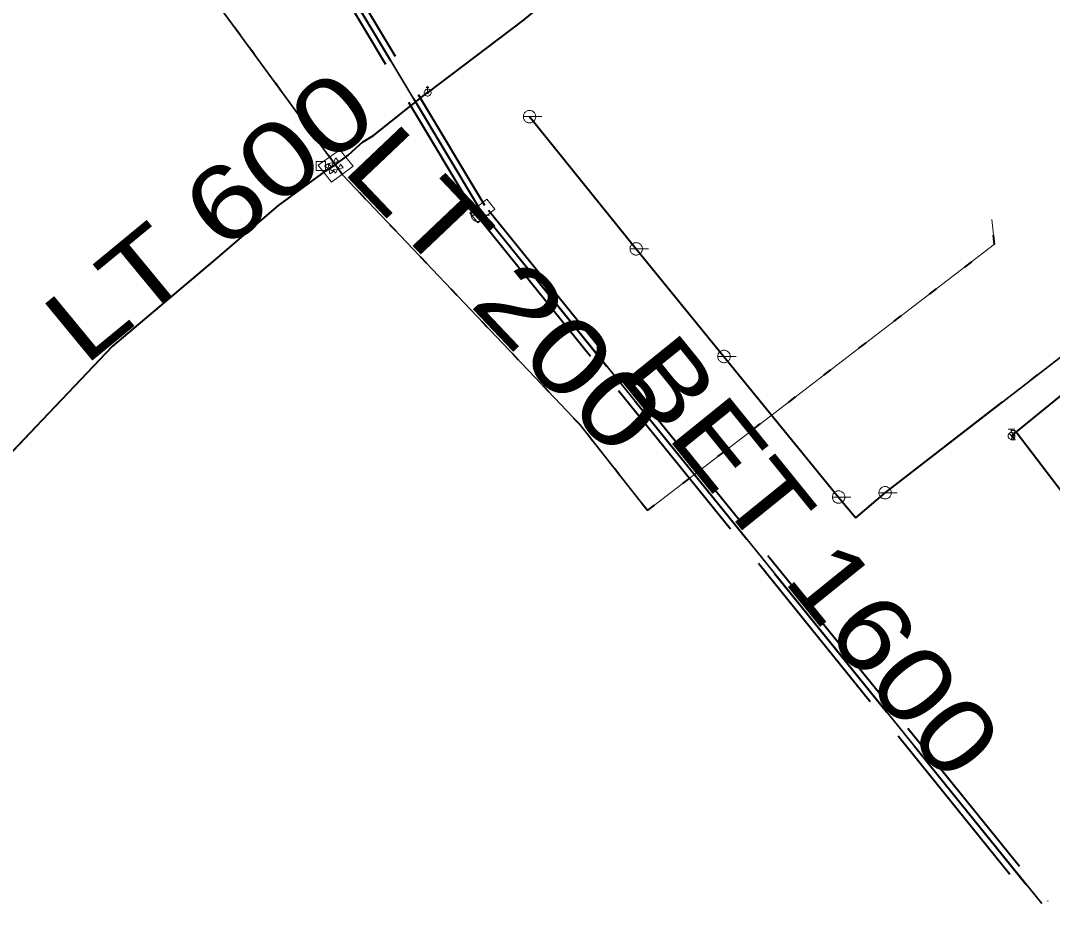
# Model space of a CAD drawing. Extents: x -968691 to -140888, y -1376050 to -879856.
# Drawn here: x -647839.9 to -647672.7, y -1059383.9 to -1059240 of the extents above; entities that cross this region are included whole.
import ezdxf
from ezdxf.enums import TextEntityAlignment as Align

# ---------------------------------------------------------------- set-up
doc = ezdxf.new("R2010")
doc.units = 0
doc.header["$LTSCALE"] = 4.8
for name, pattern in [('DASH_DOUBLE_DOT', [9.2, 5, -1.2, 0.3, -1.2, 0.3, -1.2]), ('DOTTED', [1.5, 0.3, -1.2]), ('LONG_DASHED', [7.5, 6, -1.5])]:
    doc.linetypes.add(name, pattern=pattern)
doc.layers.add('1', color=7, linetype='Continuous', lineweight=13)

msp = doc.modelspace()

# ---------------------------------------------------------------- hatches: boundary and pattern name
at = {"layer": '1'}
for points in [[(-647789.128, -1059263.115, 1), (-647789.288, -1059262.905, 1)], [(-647790.04, -1059264.101, 1), (-647789.819, -1059263.956, 1)], [(-647788.386, -1059264.131, 1), (-647788.546, -1059263.921, 1)], [(-647678.978, -1059307.23), (-647678.98, -1059307.206), (-647678.987, -1059307.183), (-647678.997, -1059307.161), (-647679.011, -1059307.142), (-647679.029, -1059307.125), (-647679.049, -1059307.112), (-647679.072, -1059307.103), (-647679.095, -1059307.099), (-647679.119, -1059307.098), (-647679.143, -1059307.102), (-647679.166, -1059307.11), (-647679.187, -1059307.122), (-647679.205, -1059307.138), (-647679.22, -1059307.157), (-647679.232, -1059307.178), (-647679.239, -1059307.201), (-647679.242, -1059307.225), (-647679.241, -1059307.249), (-647679.235, -1059307.272), (-647679.225, -1059307.294), (-647679.212, -1059307.314), (-647679.195, -1059307.331), (-647679.175, -1059307.345), (-647679.153, -1059307.355), (-647679.13, -1059307.361), (-647679.106, -1059307.362), (-647679.082, -1059307.359), (-647679.059, -1059307.352), (-647679.038, -1059307.341), (-647679.019, -1059307.326), (-647679.003, -1059307.307), (-647678.991, -1059307.287), (-647678.982, -1059307.264), (-647678.978, -1059307.24)]]:
    msp.add_hatch(color=256, dxfattribs=at).paths.add_polyline_path(points)

# ---------------------------------------------------------------- linework, layer by layer
at = {"layer": '1', "linetype": 'LONG_DASHED', "lineweight": 40}
for p, q in [((-647793.992, -1059221.085), (-647764.744, -1059269.917)), ((-647795.556, -1059222.364), (-647766.316, -1059271.182)), ((-647794.763, -1059221.744), (-647765.77, -1059270.15)), ((-647784.51, -1059259.7), (-647786.82, -1059261.82)), ((-647788.95, -1059263.39), (-647786.82, -1059261.82)), ((-647765.77, -1059270.15), (-647763.01, -1059273.68)), ((-647764.096, -1059270.746), (-647673.514, -1059382.739)), ((-647765.653, -1059272), (-647675.12, -1059383.932)), ((-647763.01, -1059273.68), (-647674.46, -1059383.16))]:
    msp.add_line(p, q, dxfattribs=at)
at = {"layer": '1', "lineweight": 35}
for p, q in [((-647794.763, -1059221.744), (-647765.77, -1059270.15)), ((-647789.208, -1059263.01), (-647804.27, -1059242.41)), ((-647784.51, -1059259.7), (-647786.82, -1059261.82)), ((-647788.95, -1059263.39), (-647789.208, -1059263.01)), ((-647788.95, -1059263.39), (-647786.82, -1059261.82)), ((-647765.77, -1059270.15), (-647763.01, -1059273.68)), ((-647763.01, -1059273.68), (-647674.46, -1059383.16)), ((-647699.84, -1059316.55), (-647668.01, -1059291.9)), ((-647666.74, -1059297), (-647678.59, -1059306.68)), ((-647704.573, -1059320.617), (-647699.84, -1059316.55))]:
    msp.add_line(p, q, dxfattribs=at)
at = {"layer": '1', "linetype": 'DOTTED', "lineweight": 40}
for p, q in [((-647789.208, -1059263.01), (-647804.27, -1059242.41)), ((-647788.95, -1059263.39), (-647789.208, -1059263.01))]:
    msp.add_line(p, q, dxfattribs=at)
at = {"layer": '1'}
for p, q in [((-647773.947, -1059251.688), (-647773.947, -1059250.696)), ((-647758.446, -1059255.581), (-647755.469, -1059255.581)), ((-647766.878, -1059271.56), (-647763.902, -1059271.56)), ((-647741.165, -1059277.018), (-647738.188, -1059277.018)), ((-647726.948, -1059294.462), (-647723.971, -1059294.462)), ((-647679.919, -1059306.271), (-647678.801, -1059306.271)), ((-647679.36, -1059306.782), (-647679.36, -1059306.271)), ((-647678.965, -1059307.736), (-647679.755, -1059306.945)), ((-647700.848, -1059316.55), (-647697.872, -1059316.55)), ((-647708.378, -1059317.25), (-647705.401, -1059317.25))]:
    msp.add_line(p, q, dxfattribs=at)
at = {"layer": '1', "linetype": 'DASH_DOUBLE_DOT'}
for p, q in [((-647791.704, -1059263.473), (-647788.166, -1059260.98)), ((-647788.166, -1059260.98), (-647786.015, -1059263.587)), ((-647789.532, -1059266.213), (-647791.704, -1059263.473)), ((-647786.015, -1059263.587), (-647789.532, -1059266.213))]:
    msp.add_line(p, q, dxfattribs=at)
at = {"layer": '1', "linetype": 'DASH_DOUBLE_DOT', "lineweight": 40}
for p, q in [((-647699.84, -1059316.55), (-647668.01, -1059291.9)), ((-647666.74, -1059297), (-647678.59, -1059306.68)), ((-647704.573, -1059320.617), (-647699.84, -1059316.55))]:
    msp.add_line(p, q, dxfattribs=at)
at = {"layer": '1', "linetype": 'DOTTED', "lineweight": 40}
for points in [[(-647804.27, -1059242.41), (-647812.48, -1059231.18), (-647819.495, -1059219.538)], [(-647738.337, -1059319.439), (-647749.311, -1059305.483), (-647787.758, -1059264.994), (-647788.466, -1059264.026), (-647788.95, -1059263.39)], [(-647738.337, -1059319.439), (-647682.104, -1059276.252), (-647682.55, -1059272.257)], [(-647678.59, -1059306.68), (-647679.11, -1059307.23), (-647679.36, -1059307.34)]]:
    msp.add_lwpolyline(points, dxfattribs=at)
at = {"layer": '1', "lineweight": 35}
for points in [[(-647804.27, -1059242.41), (-647812.48, -1059231.18), (-647819.495, -1059219.538)], [(-647773.946, -1059251.688), (-647773.795, -1059251.618), (-647758.476, -1059239.995), (-647755.985, -1059237.965), (-647755.346, -1059237.446)], [(-647784.51, -1059259.7), (-647782.725, -1059258.638), (-647773.946, -1059251.688)], [(-647757.438, -1059255.581), (-647740.157, -1059277.018), (-647725.94, -1059294.462), (-647707.37, -1059317.25), (-647704.573, -1059320.617)], [(-647790.53, -1059264.42), (-647798.147, -1059269.982), (-647808.729, -1059279.085), (-647824.987, -1059292.812), (-647847.758, -1059316.763), (-647852.291, -1059321.546), (-647857.02, -1059329.468), (-647864.807, -1059345.333), (-647870.759, -1059360.132), (-647875.166, -1059378.78)], [(-647790.53, -1059264.42), (-647789.929, -1059264.028), (-647788.95, -1059263.39)], [(-647738.337, -1059319.439), (-647749.311, -1059305.483), (-647787.758, -1059264.994), (-647788.466, -1059264.026), (-647788.95, -1059263.39)], [(-647678.59, -1059306.68), (-647658.06, -1059333.7), (-647656.38, -1059334.22), (-647654.638, -1059334.211)]]:
    msp.add_lwpolyline(points, dxfattribs=at)
at = {"layer": '1', "linetype": 'LONG_DASHED', "lineweight": 40}
for points in [[(-647773.946, -1059251.688), (-647773.795, -1059251.618), (-647758.476, -1059239.995), (-647755.985, -1059237.965), (-647755.346, -1059237.446)], [(-647784.51, -1059259.7), (-647782.725, -1059258.638), (-647773.946, -1059251.688)], [(-647790.53, -1059264.42), (-647789.929, -1059264.028), (-647788.95, -1059263.39)]]:
    msp.add_lwpolyline(points, dxfattribs=at)
at = {"layer": '1'}
for points in [[(-647773.388, -1059251.688), (-647773.396, -1059251.591), (-647773.421, -1059251.497), (-647773.463, -1059251.409), (-647773.518, -1059251.329), (-647773.587, -1059251.26), (-647773.667, -1059251.205), (-647773.755, -1059251.163), (-647773.849, -1059251.138), (-647773.946, -1059251.13), (-647774.044, -1059251.138), (-647774.138, -1059251.163), (-647774.226, -1059251.205), (-647774.306, -1059251.26), (-647774.375, -1059251.329), (-647774.43, -1059251.409), (-647774.472, -1059251.497), (-647774.497, -1059251.591), (-647774.505, -1059251.688), (-647774.497, -1059251.786), (-647774.472, -1059251.88), (-647774.43, -1059251.968), (-647774.375, -1059252.048), (-647774.306, -1059252.117), (-647774.226, -1059252.172), (-647774.138, -1059252.214), (-647774.044, -1059252.239), (-647773.946, -1059252.247), (-647773.849, -1059252.239), (-647773.755, -1059252.214), (-647773.667, -1059252.172), (-647773.587, -1059252.117), (-647773.518, -1059252.048), (-647773.463, -1059251.968), (-647773.421, -1059251.88), (-647773.396, -1059251.786)], [(-647773.815, -1059251.688), (-647773.817, -1059251.665), (-647773.823, -1059251.643), (-647773.833, -1059251.622), (-647773.846, -1059251.603), (-647773.862, -1059251.587), (-647773.881, -1059251.574), (-647773.902, -1059251.564), (-647773.924, -1059251.558), (-647773.947, -1059251.556), (-647773.97, -1059251.558), (-647773.992, -1059251.564), (-647774.013, -1059251.574), (-647774.032, -1059251.587), (-647774.048, -1059251.603), (-647774.061, -1059251.622), (-647774.071, -1059251.643), (-647774.077, -1059251.665), (-647774.079, -1059251.688), (-647774.077, -1059251.711), (-647774.071, -1059251.733), (-647774.061, -1059251.754), (-647774.048, -1059251.773), (-647774.032, -1059251.789), (-647774.013, -1059251.802), (-647773.992, -1059251.812), (-647773.97, -1059251.818), (-647773.947, -1059251.82), (-647773.924, -1059251.818), (-647773.902, -1059251.812), (-647773.881, -1059251.802), (-647773.862, -1059251.789), (-647773.846, -1059251.773), (-647773.833, -1059251.754), (-647773.823, -1059251.733), (-647773.817, -1059251.711)], [(-647757.438, -1059254.573), (-647757.543, -1059254.579), (-647757.647, -1059254.595), (-647757.749, -1059254.622), (-647757.847, -1059254.66), (-647757.941, -1059254.708), (-647758.029, -1059254.765), (-647758.112, -1059254.832), (-647758.187, -1059254.907), (-647758.253, -1059254.989), (-647758.31, -1059255.076), (-647758.357, -1059255.171), (-647758.395, -1059255.27), (-647758.423, -1059255.371), (-647758.439, -1059255.476), (-647758.446, -1059255.581), (-647758.439, -1059255.686), (-647758.423, -1059255.791), (-647758.395, -1059255.893), (-647758.357, -1059255.991), (-647758.31, -1059256.084), (-647758.253, -1059256.174), (-647758.187, -1059256.256), (-647758.112, -1059256.33), (-647758.029, -1059256.396), (-647757.941, -1059256.454), (-647757.847, -1059256.502), (-647757.749, -1059256.54), (-647757.647, -1059256.567), (-647757.543, -1059256.583), (-647757.438, -1059256.589), (-647757.332, -1059256.583), (-647757.227, -1059256.567), (-647757.126, -1059256.54), (-647757.028, -1059256.502), (-647756.933, -1059256.454), (-647756.845, -1059256.396), (-647756.763, -1059256.33), (-647756.688, -1059256.256), (-647756.622, -1059256.174), (-647756.565, -1059256.084), (-647756.516, -1059255.991), (-647756.478, -1059255.893), (-647756.452, -1059255.791), (-647756.436, -1059255.686), (-647756.43, -1059255.581), (-647756.436, -1059255.476), (-647756.452, -1059255.371), (-647756.478, -1059255.27), (-647756.516, -1059255.171), (-647756.565, -1059255.076), (-647756.622, -1059254.989), (-647756.688, -1059254.907), (-647756.763, -1059254.832), (-647756.845, -1059254.765), (-647756.933, -1059254.708), (-647757.028, -1059254.66), (-647757.126, -1059254.622), (-647757.227, -1059254.595), (-647757.332, -1059254.579)], [(-647791.989, -1059264.326), (-647790.489, -1059264.326), (-647790.489, -1059262.826), (-647791.989, -1059262.826)], [(-647789.226, -1059264.465), (-647789.813, -1059264.847), (-647790.045, -1059263.209), (-647790.632, -1059263.591)], [(-647788.821, -1059262.278), (-647788.399, -1059262.836), (-647790.017, -1059263.184), (-647789.595, -1059263.742)], [(-647788.079, -1059263.294), (-647787.657, -1059263.852), (-647789.275, -1059264.2), (-647788.853, -1059264.758)], [(-647765.87, -1059270.552), (-647765.975, -1059270.558), (-647766.079, -1059270.574), (-647766.181, -1059270.602), (-647766.28, -1059270.64), (-647766.374, -1059270.687), (-647766.462, -1059270.745), (-647766.544, -1059270.811), (-647766.619, -1059270.886), (-647766.685, -1059270.968), (-647766.743, -1059271.056), (-647766.79, -1059271.15), (-647766.828, -1059271.249), (-647766.856, -1059271.351), (-647766.872, -1059271.455), (-647766.878, -1059271.56), (-647766.872, -1059271.665), (-647766.856, -1059271.77), (-647766.828, -1059271.872), (-647766.79, -1059271.97), (-647766.743, -1059272.064), (-647766.685, -1059272.153), (-647766.619, -1059272.235), (-647766.544, -1059272.309), (-647766.462, -1059272.375), (-647766.374, -1059272.433), (-647766.28, -1059272.481), (-647766.181, -1059272.519), (-647766.079, -1059272.546), (-647765.975, -1059272.562), (-647765.87, -1059272.568), (-647765.765, -1059272.562), (-647765.66, -1059272.546), (-647765.558, -1059272.519), (-647765.46, -1059272.481), (-647765.366, -1059272.433), (-647765.277, -1059272.375), (-647765.195, -1059272.309), (-647765.121, -1059272.235), (-647765.055, -1059272.153), (-647764.997, -1059272.064), (-647764.949, -1059271.97), (-647764.911, -1059271.872), (-647764.884, -1059271.77), (-647764.868, -1059271.665), (-647764.862, -1059271.56), (-647764.868, -1059271.455), (-647764.884, -1059271.351), (-647764.911, -1059271.249), (-647764.949, -1059271.15), (-647764.997, -1059271.056), (-647765.055, -1059270.968), (-647765.121, -1059270.886), (-647765.195, -1059270.811), (-647765.277, -1059270.745), (-647765.366, -1059270.687), (-647765.46, -1059270.64), (-647765.558, -1059270.602), (-647765.66, -1059270.574), (-647765.765, -1059270.558)], [(-647740.157, -1059276.01), (-647740.262, -1059276.016), (-647740.366, -1059276.032), (-647740.468, -1059276.059), (-647740.566, -1059276.097), (-647740.66, -1059276.145), (-647740.748, -1059276.202), (-647740.831, -1059276.269), (-647740.906, -1059276.344), (-647740.972, -1059276.426), (-647741.029, -1059276.513), (-647741.076, -1059276.608), (-647741.114, -1059276.707), (-647741.142, -1059276.808), (-647741.158, -1059276.913), (-647741.165, -1059277.018), (-647741.158, -1059277.123), (-647741.142, -1059277.228), (-647741.114, -1059277.33), (-647741.076, -1059277.428), (-647741.029, -1059277.521), (-647740.972, -1059277.611), (-647740.906, -1059277.693), (-647740.831, -1059277.767), (-647740.748, -1059277.833), (-647740.66, -1059277.891), (-647740.566, -1059277.939), (-647740.468, -1059277.977), (-647740.366, -1059278.004), (-647740.262, -1059278.02), (-647740.157, -1059278.026), (-647740.051, -1059278.02), (-647739.946, -1059278.004), (-647739.845, -1059277.977), (-647739.747, -1059277.939), (-647739.652, -1059277.891), (-647739.564, -1059277.833), (-647739.482, -1059277.767), (-647739.407, -1059277.693), (-647739.341, -1059277.611), (-647739.284, -1059277.521), (-647739.235, -1059277.428), (-647739.197, -1059277.33), (-647739.171, -1059277.228), (-647739.155, -1059277.123), (-647739.149, -1059277.018), (-647739.155, -1059276.913), (-647739.171, -1059276.808), (-647739.197, -1059276.707), (-647739.235, -1059276.608), (-647739.284, -1059276.513), (-647739.341, -1059276.426), (-647739.407, -1059276.344), (-647739.482, -1059276.269), (-647739.564, -1059276.202), (-647739.652, -1059276.145), (-647739.747, -1059276.097), (-647739.845, -1059276.059), (-647739.946, -1059276.032), (-647740.051, -1059276.016)], [(-647725.94, -1059293.454), (-647726.045, -1059293.46), (-647726.149, -1059293.476), (-647726.251, -1059293.503), (-647726.349, -1059293.541), (-647726.443, -1059293.589), (-647726.531, -1059293.646), (-647726.614, -1059293.713), (-647726.689, -1059293.788), (-647726.755, -1059293.87), (-647726.812, -1059293.957), (-647726.859, -1059294.052), (-647726.897, -1059294.151), (-647726.925, -1059294.252), (-647726.941, -1059294.357), (-647726.948, -1059294.462), (-647726.941, -1059294.567), (-647726.925, -1059294.672), (-647726.897, -1059294.774), (-647726.859, -1059294.872), (-647726.812, -1059294.965), (-647726.755, -1059295.055), (-647726.689, -1059295.137), (-647726.614, -1059295.211), (-647726.531, -1059295.277), (-647726.443, -1059295.335), (-647726.349, -1059295.383), (-647726.251, -1059295.421), (-647726.149, -1059295.448), (-647726.045, -1059295.464), (-647725.94, -1059295.47), (-647725.834, -1059295.464), (-647725.729, -1059295.448), (-647725.628, -1059295.421), (-647725.53, -1059295.383), (-647725.435, -1059295.335), (-647725.347, -1059295.277), (-647725.265, -1059295.211), (-647725.19, -1059295.137), (-647725.124, -1059295.055), (-647725.067, -1059294.965), (-647725.018, -1059294.872), (-647724.98, -1059294.774), (-647724.954, -1059294.672), (-647724.938, -1059294.567), (-647724.932, -1059294.462), (-647724.938, -1059294.357), (-647724.954, -1059294.252), (-647724.98, -1059294.151), (-647725.018, -1059294.052), (-647725.067, -1059293.957), (-647725.124, -1059293.87), (-647725.19, -1059293.788), (-647725.265, -1059293.713), (-647725.347, -1059293.646), (-647725.435, -1059293.589), (-647725.53, -1059293.541), (-647725.628, -1059293.503), (-647725.729, -1059293.476), (-647725.834, -1059293.46)], [(-647679.46, -1059306.48), (-647678.76, -1059306.48), (-647679.46, -1059307.98), (-647678.76, -1059307.98)], [(-647678.801, -1059307.341), (-647678.81, -1059307.244), (-647678.835, -1059307.15), (-647678.876, -1059307.062), (-647678.932, -1059306.982), (-647679.001, -1059306.913), (-647679.081, -1059306.857), (-647679.169, -1059306.816), (-647679.263, -1059306.791), (-647679.36, -1059306.782), (-647679.457, -1059306.791), (-647679.551, -1059306.816), (-647679.639, -1059306.857), (-647679.719, -1059306.913), (-647679.788, -1059306.982), (-647679.844, -1059307.062), (-647679.885, -1059307.15), (-647679.91, -1059307.244), (-647679.919, -1059307.341), (-647679.91, -1059307.438), (-647679.885, -1059307.532), (-647679.844, -1059307.62), (-647679.788, -1059307.7), (-647679.719, -1059307.769), (-647679.639, -1059307.825), (-647679.551, -1059307.866), (-647679.457, -1059307.891), (-647679.36, -1059307.899), (-647679.263, -1059307.891), (-647679.169, -1059307.866), (-647679.081, -1059307.825), (-647679.001, -1059307.769), (-647678.932, -1059307.7), (-647678.876, -1059307.62), (-647678.835, -1059307.532), (-647678.81, -1059307.438)], [(-647678.978, -1059307.23), (-647678.98, -1059307.206), (-647678.987, -1059307.183), (-647678.997, -1059307.161), (-647679.011, -1059307.142), (-647679.029, -1059307.125), (-647679.049, -1059307.112), (-647679.072, -1059307.103), (-647679.095, -1059307.099), (-647679.119, -1059307.098), (-647679.143, -1059307.102), (-647679.166, -1059307.11), (-647679.187, -1059307.122), (-647679.205, -1059307.138), (-647679.22, -1059307.157), (-647679.232, -1059307.178), (-647679.239, -1059307.201), (-647679.242, -1059307.225), (-647679.241, -1059307.249), (-647679.235, -1059307.272), (-647679.225, -1059307.294), (-647679.212, -1059307.314), (-647679.195, -1059307.331), (-647679.175, -1059307.345), (-647679.153, -1059307.355), (-647679.13, -1059307.361), (-647679.106, -1059307.362), (-647679.082, -1059307.359), (-647679.059, -1059307.352), (-647679.038, -1059307.341), (-647679.019, -1059307.326), (-647679.003, -1059307.307), (-647678.991, -1059307.287), (-647678.982, -1059307.264), (-647678.978, -1059307.24)], [(-647707.37, -1059316.242), (-647707.475, -1059316.248), (-647707.579, -1059316.264), (-647707.681, -1059316.291), (-647707.779, -1059316.329), (-647707.873, -1059316.377), (-647707.961, -1059316.434), (-647708.044, -1059316.501), (-647708.119, -1059316.576), (-647708.185, -1059316.658), (-647708.242, -1059316.745), (-647708.289, -1059316.84), (-647708.327, -1059316.939), (-647708.355, -1059317.04), (-647708.371, -1059317.145), (-647708.378, -1059317.25), (-647708.371, -1059317.355), (-647708.355, -1059317.46), (-647708.327, -1059317.562), (-647708.289, -1059317.66), (-647708.242, -1059317.753), (-647708.185, -1059317.843), (-647708.119, -1059317.925), (-647708.044, -1059317.999), (-647707.961, -1059318.065), (-647707.873, -1059318.123), (-647707.779, -1059318.171), (-647707.681, -1059318.209), (-647707.579, -1059318.236), (-647707.475, -1059318.252), (-647707.37, -1059318.258), (-647707.264, -1059318.252), (-647707.159, -1059318.236), (-647707.058, -1059318.209), (-647706.96, -1059318.171), (-647706.865, -1059318.123), (-647706.777, -1059318.065), (-647706.695, -1059317.999), (-647706.62, -1059317.925), (-647706.554, -1059317.843), (-647706.497, -1059317.753), (-647706.448, -1059317.66), (-647706.41, -1059317.562), (-647706.384, -1059317.46), (-647706.368, -1059317.355), (-647706.362, -1059317.25), (-647706.368, -1059317.145), (-647706.384, -1059317.04), (-647706.41, -1059316.939), (-647706.448, -1059316.84), (-647706.497, -1059316.745), (-647706.554, -1059316.658), (-647706.62, -1059316.576), (-647706.695, -1059316.501), (-647706.777, -1059316.434), (-647706.865, -1059316.377), (-647706.96, -1059316.329), (-647707.058, -1059316.291), (-647707.159, -1059316.264), (-647707.264, -1059316.248)], [(-647699.84, -1059315.542), (-647699.945, -1059315.548), (-647700.049, -1059315.564), (-647700.151, -1059315.592), (-647700.25, -1059315.63), (-647700.344, -1059315.677), (-647700.432, -1059315.735), (-647700.514, -1059315.801), (-647700.589, -1059315.876), (-647700.655, -1059315.958), (-647700.713, -1059316.046), (-647700.76, -1059316.14), (-647700.798, -1059316.239), (-647700.826, -1059316.341), (-647700.842, -1059316.445), (-647700.848, -1059316.55), (-647700.842, -1059316.655), (-647700.826, -1059316.76), (-647700.798, -1059316.862), (-647700.76, -1059316.96), (-647700.713, -1059317.054), (-647700.655, -1059317.143), (-647700.589, -1059317.225), (-647700.514, -1059317.299), (-647700.432, -1059317.365), (-647700.344, -1059317.423), (-647700.25, -1059317.471), (-647700.151, -1059317.509), (-647700.049, -1059317.536), (-647699.945, -1059317.552), (-647699.84, -1059317.558), (-647699.735, -1059317.552), (-647699.63, -1059317.536), (-647699.528, -1059317.509), (-647699.43, -1059317.471), (-647699.336, -1059317.423), (-647699.247, -1059317.365), (-647699.165, -1059317.299), (-647699.091, -1059317.225), (-647699.025, -1059317.143), (-647698.967, -1059317.054), (-647698.919, -1059316.96), (-647698.881, -1059316.862), (-647698.854, -1059316.76), (-647698.838, -1059316.655), (-647698.832, -1059316.55), (-647698.838, -1059316.445), (-647698.854, -1059316.341), (-647698.881, -1059316.239), (-647698.919, -1059316.14), (-647698.967, -1059316.046), (-647699.025, -1059315.958), (-647699.091, -1059315.876), (-647699.165, -1059315.801), (-647699.247, -1059315.735), (-647699.336, -1059315.677), (-647699.43, -1059315.63), (-647699.528, -1059315.592), (-647699.63, -1059315.564), (-647699.735, -1059315.548)]]:
    msp.add_lwpolyline(points, close=True, dxfattribs=at)
for points in [[(-647773.729, -1059250.914), (-647773.947, -1059250.696), (-647774.165, -1059250.914)], [(-647738.337, -1059319.439), (-647682.104, -1059276.252), (-647682.55, -1059272.257)], [(-647678.59, -1059306.68), (-647679.11, -1059307.23), (-647679.36, -1059307.34)]]:
    msp.add_lwpolyline(points, dxfattribs=at)
at = {"layer": '1', "lineweight": 40}
msp.add_lwpolyline([(-647757.438, -1059255.581), (-647740.157, -1059277.018), (-647725.94, -1059294.462), (-647707.37, -1059317.25), (-647704.573, -1059320.617)], dxfattribs=at)
at = {"layer": '1', "linetype": 'DASH_DOUBLE_DOT', "lineweight": 40}
for points in [[(-647790.53, -1059264.42), (-647798.147, -1059269.982), (-647808.729, -1059279.085), (-647824.987, -1059292.812), (-647847.758, -1059316.763), (-647852.291, -1059321.546), (-647857.02, -1059329.468), (-647864.807, -1059345.333), (-647870.759, -1059360.132), (-647875.166, -1059378.78)], [(-647678.59, -1059306.68), (-647658.06, -1059333.7), (-647656.38, -1059334.22), (-647654.638, -1059334.211)]]:
    msp.add_lwpolyline(points, dxfattribs=at)
at = {"layer": '1', "linetype": 'LONG_DASHED'}
msp.add_lwpolyline([(-647764.374, -1059268.976), (-647767.102, -1059271.174), (-647765.815, -1059272.773), (-647763.087, -1059270.575)], close=True, dxfattribs=at)
at = {"layer": '1'}
for centre in [(-647789.208, -1059263.01), (-647789.929, -1059264.028), (-647788.466, -1059264.026)]:
    msp.add_circle(centre, 0.132, dxfattribs=at)

# ---------------------------------------------------------------- texts
for s, rotation, width, p in [('LT 600', 39.488, 1.25, (-647805.444, -1059276.32)), ('LT 200', 313.518, 1.3, (-647765.741, -1059287.743)), ('BET 1600', 308.967, 1.2, (-647716.499, -1059330.707))]:
    msp.add_text(s, height=12, rotation=rotation, dxfattribs=dict(at, width=width)).set_placement(p, align=Align.CENTER)

doc.saveas('drawing.dxf')
